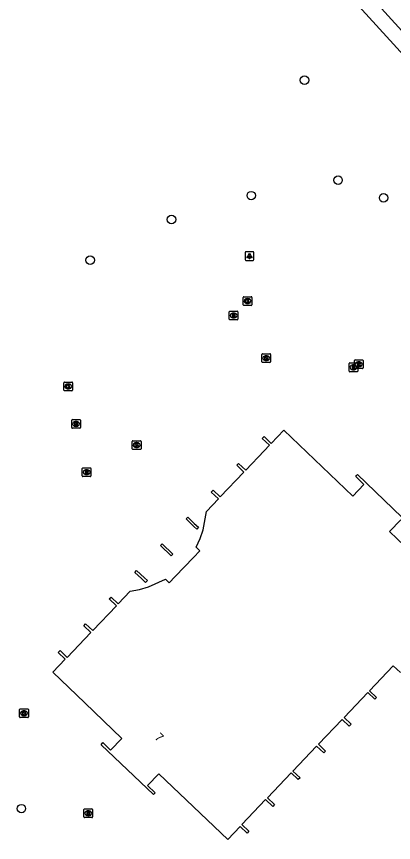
# Model space of a CAD drawing. Extents: x 156061 to 157804, y 383451 to 385640.
# Drawn here: x 156744.7 to 156788, y 385074 to 385169 of the extents above; entities that cross this region are included whole.
import ezdxf

# ---------------------------------------------------------------- set-up
doc = ezdxf.new("R2010")
doc.units = 0
for name, color, linetype in [('IMGEO_Boom', 7, 'Continuous'), ('IMGEO_Groenvoorziening', 7, 'Continuous'), ('IMGEO_Kolk', 7, 'Continuous'), ('IMGEO_Lichtpunt', 7, 'Continuous'), ('IMGEO_Muur', 7, 'Continuous'), ('IMGEO_Pand', 7, 'Continuous'), ('IMGEO_Pand_nummerreeks', 7, 'Continuous'), ('IMGEO_Rioolput', 7, 'Continuous')]:
    doc.layers.add(name, color=color, linetype=linetype)

msp = doc.modelspace()

# ---------------------------------------------------------------- linework, layer by layer
at = {"layer": 'IMGEO_Boom'}
for centre in [(156777.789, 385161.673), (156781.652, 385150.175), (156771.679, 385148.407), (156786.886, 385148.15), (156762.496, 385145.654), (156753.154, 385140.988), (156745.247, 385077.936)]:
    msp.add_circle(centre, 0.489, dxfattribs=at)
at = {"layer": 'IMGEO_Groenvoorziening'}
for points in [[(156761.368, 385197.864), (156769.389, 385188.869), (156788.986, 385167.342), (156795.719, 385160.38), (156801.201, 385154.555), (156810.516, 385145.054), (156813.592, 385141.799), (156814.804, 385140.338), (156816.368, 385138.907), (156818.343, 385137.378), (156819.322, 385136.23), (156819.794, 385135.425), (156822.114, 385133.429), (156843.396, 385112.468), (156845.278, 385111.354), (156860.479, 385096.242), (156876.719, 385081.077), (156890.203, 385068.13), (156896.136, 385062.583), (156899.441, 385059.57)], [(156717.677, 385063.118), (156717.97, 385063.009), (156717.781, 385062.506), (156718.696, 385062.163), (156718.88, 385062.654), (156870.373, 385006.508), (156870.967, 385006.288), (156875.119, 385016.625), (156892.549, 385064.295), (156865.99, 385088.285), (156852.111, 385101.789), (156804.773, 385147.48), (156780.437, 385174.157), (156759.871, 385196.529)]]:
    msp.add_lwpolyline(points, dxfattribs=at)
at = {"layer": 'IMGEO_Kolk'}
for p, q in [((156770.818, 385136.787), (156771.67, 385136.787)), ((156770.743, 385135.861), (156770.743, 385136.713)), ((156771.67, 385135.787), (156770.818, 385135.787)), ((156771.254, 385136.007), (156771.229, 385136.007)), ((156771.231, 385136.567), (156771.256, 385136.567)), ((156771.744, 385136.713), (156771.744, 385135.861)), ((156772.898, 385129.299), (156772.898, 385130.151)), ((156772.973, 385130.225), (156773.825, 385130.225)), ((156773.899, 385130.151), (156773.899, 385129.299)), ((156773.825, 385129.225), (156772.973, 385129.225)), ((156773.409, 385129.445), (156773.384, 385129.445)), ((156773.386, 385130.005), (156773.411, 385130.005)), ((156750.131, 385126.051), (156750.131, 385126.903)), ((156750.206, 385126.977), (156751.058, 385126.977)), ((156750.619, 385126.757), (156750.644, 385126.757)), ((156751.132, 385126.903), (156751.132, 385126.051)), ((156751.058, 385125.977), (156750.206, 385125.977)), ((156750.642, 385126.197), (156750.617, 385126.197)), ((156758.003, 385119.308), (156758.003, 385120.16)), ((156758.078, 385120.234), (156758.93, 385120.234)), ((156758.491, 385120.014), (156758.516, 385120.014)), ((156759.004, 385120.16), (156759.004, 385119.308)), ((156758.93, 385119.234), (156758.078, 385119.234)), ((156758.514, 385119.454), (156758.489, 385119.454)), ((156745.049, 385088.477), (156745.049, 385089.329)), ((156745.124, 385089.403), (156745.976, 385089.403)), ((156746.05, 385089.329), (156746.05, 385088.477)), ((156745.976, 385088.403), (156745.124, 385088.403)), ((156745.56, 385088.623), (156745.535, 385088.623)), ((156745.537, 385089.183), (156745.562, 385089.183))]:
    msp.add_line(p, q, dxfattribs=at)
for points in [[(156770.818, 385136.787), (156771.67, 385136.787)], [(156770.743, 385135.861), (156770.743, 385136.713)], [(156771.67, 385135.787), (156770.818, 385135.787)], [(156771.064, 385136.487), (156771.187, 385136.487), (156771.187, 385136.336), (156771.317, 385136.487), (156771.481, 385136.487), (156771.335, 385136.336), (156771.488, 385136.087), (156771.336, 385136.087), (156771.251, 385136.251), (156771.187, 385136.184), (156771.187, 385136.087), (156771.064, 385136.087), (156771.064, 385136.487)], [(156771.744, 385136.713), (156771.744, 385135.861)], [(156772.898, 385129.299), (156772.898, 385130.151)], [(156772.973, 385130.225), (156773.825, 385130.225)], [(156773.899, 385130.151), (156773.899, 385129.299)], [(156773.825, 385129.225), (156772.973, 385129.225)], [(156773.219, 385129.925), (156773.342, 385129.925), (156773.342, 385129.774), (156773.472, 385129.925), (156773.636, 385129.925), (156773.49, 385129.774), (156773.643, 385129.525), (156773.491, 385129.525), (156773.406, 385129.689), (156773.342, 385129.622), (156773.342, 385129.525), (156773.219, 385129.525), (156773.219, 385129.925)], [(156750.131, 385126.051), (156750.131, 385126.903)], [(156750.206, 385126.977), (156751.058, 385126.977)], [(156750.452, 385126.677), (156750.575, 385126.677), (156750.575, 385126.526), (156750.705, 385126.677), (156750.869, 385126.677), (156750.723, 385126.526), (156750.876, 385126.277), (156750.724, 385126.277), (156750.639, 385126.441), (156750.575, 385126.374), (156750.575, 385126.277), (156750.452, 385126.277), (156750.452, 385126.677)], [(156751.132, 385126.903), (156751.132, 385126.051)], [(156751.058, 385125.977), (156750.206, 385125.977)], [(156758.003, 385119.308), (156758.003, 385120.16)], [(156758.078, 385120.234), (156758.93, 385120.234)], [(156758.324, 385119.934), (156758.447, 385119.934), (156758.447, 385119.783), (156758.577, 385119.934), (156758.741, 385119.934), (156758.595, 385119.783), (156758.748, 385119.534), (156758.596, 385119.534), (156758.511, 385119.698), (156758.447, 385119.631), (156758.447, 385119.534), (156758.324, 385119.534), (156758.324, 385119.934)], [(156759.004, 385120.16), (156759.004, 385119.308)], [(156758.93, 385119.234), (156758.078, 385119.234)], [(156745.049, 385088.477), (156745.049, 385089.329)], [(156745.124, 385089.403), (156745.976, 385089.403)], [(156746.05, 385089.329), (156746.05, 385088.477)], [(156745.976, 385088.403), (156745.124, 385088.403)], [(156745.37, 385089.103), (156745.493, 385089.103), (156745.493, 385088.952), (156745.623, 385089.103), (156745.787, 385089.103), (156745.641, 385088.952), (156745.794, 385088.703), (156745.642, 385088.703), (156745.557, 385088.867), (156745.493, 385088.8), (156745.493, 385088.703), (156745.37, 385088.703), (156745.37, 385089.103)]]:
    msp.add_lwpolyline(points, dxfattribs=at)
for centre, start, end in [((156770.82, 385136.711), 91.55205, 178.44795), ((156770.82, 385136.711), 91.55205, 178.44795), ((156771.668, 385136.711), 1.55205, 88.44795), ((156771.668, 385136.711), 1.55205, 88.44795), ((156770.82, 385135.863), 181.55205, 268.44795), ((156770.82, 385135.863), 181.55205, 268.44795), ((156771.668, 385135.863), 271.55205, 358.44795), ((156771.668, 385135.863), 271.55205, 358.44795), ((156772.975, 385130.149), 91.55205, 178.44795), ((156772.975, 385130.149), 91.55205, 178.44795), ((156773.823, 385130.149), 1.55205, 88.44795), ((156773.823, 385130.149), 1.55205, 88.44795), ((156772.975, 385129.301), 181.55205, 268.44795), ((156772.975, 385129.301), 181.55205, 268.44795), ((156773.823, 385129.301), 271.55205, 358.44795), ((156773.823, 385129.301), 271.55205, 358.44795), ((156750.208, 385126.901), 91.55205, 178.44795), ((156750.208, 385126.901), 91.55205, 178.44795), ((156751.056, 385126.901), 1.55205, 88.44795), ((156751.056, 385126.901), 1.55205, 88.44795), ((156750.208, 385126.053), 181.55205, 268.44795), ((156750.208, 385126.053), 181.55205, 268.44795), ((156751.056, 385126.053), 271.55205, 358.44795), ((156751.056, 385126.053), 271.55205, 358.44795), ((156758.08, 385120.158), 91.55205, 178.44795), ((156758.08, 385120.158), 91.55205, 178.44795), ((156758.928, 385120.158), 1.55205, 88.44795), ((156758.928, 385120.158), 1.55205, 88.44795), ((156758.08, 385119.31), 181.55205, 268.44795), ((156758.08, 385119.31), 181.55205, 268.44795), ((156758.928, 385119.31), 271.55205, 358.44795), ((156758.928, 385119.31), 271.55205, 358.44795), ((156745.126, 385089.327), 91.55205, 178.44795), ((156745.126, 385089.327), 91.55205, 178.44795), ((156745.974, 385089.327), 1.55205, 88.44795), ((156745.974, 385089.327), 1.55205, 88.44795), ((156745.126, 385088.479), 181.55205, 268.44795), ((156745.126, 385088.479), 181.55205, 268.44795), ((156745.974, 385088.479), 271.55205, 358.44795), ((156745.974, 385088.479), 271.55205, 358.44795)]:
    msp.add_arc(centre, 0.0765, start, end, dxfattribs=at)
for centre, major_axis, ratio, start_param, end_param in [((156771.23, 385136.287), (-0.387, 0.002), 0.722429, 4.712389, 7.853982), ((156771.255, 385136.287), (-0.39, 0.002), 0.717154, 1.570796, 4.712389), ((156773.385, 385129.725), (-0.387, 0.002), 0.722429, 4.712389, 7.853982), ((156773.41, 385129.725), (-0.39, 0.002), 0.717154, 1.570796, 4.712389), ((156750.618, 385126.477), (-0.387, 0.002), 0.722429, 4.712389, 7.853982), ((156750.643, 385126.477), (-0.39, 0.002), 0.717154, 1.570796, 4.712389), ((156758.49, 385119.734), (-0.387, 0.002), 0.722429, 4.712389, 7.853982), ((156758.515, 385119.734), (-0.39, 0.002), 0.717154, 1.570796, 4.712389), ((156745.536, 385088.903), (-0.387, 0.002), 0.722429, 4.712389, 7.853982), ((156745.561, 385088.903), (-0.39, 0.002), 0.717154, 1.570796, 4.712389)]:
    msp.add_ellipse(centre, major_axis=major_axis, ratio=ratio, start_param=start_param, end_param=end_param, dxfattribs=at)
at = {"layer": 'IMGEO_Lichtpunt'}
for p, q in [((156770.972, 385141.864), (156770.972, 385141.057)), ((156770.972, 385141.864), (156770.972, 385141.057)), ((156771.874, 385141.959), (156771.066, 385141.959)), ((156771.874, 385141.959), (156771.066, 385141.959)), ((156771.968, 385141.057), (156771.968, 385141.864)), ((156771.968, 385141.057), (156771.968, 385141.864)), ((156771.066, 385140.963), (156771.874, 385140.963)), ((156771.066, 385140.963), (156771.874, 385140.963))]:
    msp.add_line(p, q, dxfattribs=at)
for points in [[(156771.346, 385141.528), (156771.385, 385141.5), (156771.197, 385141.238), (156771.159, 385141.265), (156771.346, 385141.528)], [(156771.448, 385141.48), (156771.495, 385141.48), (156771.495, 385141.158), (156771.448, 385141.158), (156771.448, 385141.48)], [(156771.558, 385141.5), (156771.596, 385141.527), (156771.783, 385141.265), (156771.744, 385141.237), (156771.558, 385141.5)]]:
    msp.add_lwpolyline(points, dxfattribs=at)
msp.add_circle((156771.471, 385141.662), 0.0994, dxfattribs=at)
for centre, start, end in [((156771.066, 385141.864), 90, 180), ((156771.066, 385141.864), 90, 180), ((156771.874, 385141.864), 0, 90), ((156771.874, 385141.864), 0, 90), ((156771.066, 385141.057), 180, 270), ((156771.066, 385141.057), 180, 270), ((156771.874, 385141.057), 270, 0), ((156771.874, 385141.057), 270, 360)]:
    msp.add_arc(centre, 0.0946, start, end, dxfattribs=at)
at = {"layer": 'IMGEO_Muur'}
msp.add_lwpolyline([(156875.119, 385016.625), (156892.549, 385064.295), (156865.99, 385088.285), (156852.111, 385101.789), (156804.773, 385147.48), (156780.437, 385174.157), (156759.871, 385196.529)], dxfattribs=at)
at = {"layer": 'IMGEO_Pand'}
for points in [[(156776.469, 385082.264), (156777.28, 385081.491), (156777.073, 385081.274), (156776.262, 385082.047), (156773.535, 385079.189), (156774.346, 385078.416), (156774.139, 385078.199), (156773.328, 385078.972), (156770.601, 385076.114), (156771.412, 385075.341), (156771.205, 385075.124), (156770.394, 385075.897), (156768.968, 385074.402), (156761.046, 385081.957), (156759.76, 385080.603), (156760.645, 385079.768), (156760.425, 385079.549), (156754.405, 385085.261), (156754.626, 385085.527), (156755.503, 385084.662), (156756.803, 385086.009), (156754.676, 385088.049), (156752.53, 385090.107), (156748.874, 385093.614), (156750.296, 385095.106), (156749.486, 385095.879), (156749.699, 385096.103), (156750.509, 385095.33), (156753.234, 385098.19), (156752.424, 385098.963), (156752.638, 385099.187), (156753.448, 385098.414), (156756.166, 385101.267), (156755.356, 385102.04), (156755.563, 385102.257), (156756.373, 385101.484), (156757.769, 385102.949), (156758.836, 385103.138), (156759.851, 385103.431), (156761.8, 385104.331), (156762.254, 385103.908), (156762.945, 385104.624), (156765.052, 385106.806), (156765.778, 385107.557), (156765.322, 385107.998), (156765.792, 385108.99), (156766.141, 385110), (156766.514, 385112.109), (156767.894, 385113.558), (156767.083, 385114.331), (156767.29, 385114.548), (156768.101, 385113.775), (156770.825, 385116.635), (156770.014, 385117.408), (156770.221, 385117.625), (156771.032, 385116.852), (156773.16, 385119.087), (156773.756, 385119.713), (156772.945, 385120.486), (156773.152, 385120.703), (156773.963, 385119.93), (156775.408, 385121.447), (156783.345, 385113.844), (156784.629, 385115.205), (156783.69, 385116.135), (156783.785, 385116.24), (156783.897, 385116.364), (156790.031, 385110.462)], [(156765.401, 385110.061), (156765.065, 385110.37), (156764.175, 385111.241), (156764.37, 385111.451), (156765.12, 385110.733), (156765.605, 385110.279), (156765.401, 385110.061)], [(156788.853, 385111.154), (156787.582, 385109.808), (156795.507, 385102.218)], [(156761.243, 385108.182), (156761.444, 385108.383), (156762.656, 385107.209), (156762.467, 385106.999), (156761.243, 385108.182)], [(156758.303, 385105.094), (156758.501, 385105.323), (156759.413, 385104.478), (156759.74, 385104.157), (156759.526, 385103.94), (156759.041, 385104.39), (156758.303, 385105.094)], [(156788.815, 385093.581), (156788.004, 385094.354), (156785.277, 385091.496), (156786.088, 385090.723), (156785.881, 385090.506), (156785.07, 385091.279), (156782.337, 385088.414), (156783.148, 385087.641), (156782.94, 385087.424), (156782.129, 385088.197), (156779.396, 385085.332), (156780.207, 385084.559), (156780, 385084.341), (156779.189, 385085.114), (156776.469, 385082.264)]]:
    msp.add_lwpolyline(points, dxfattribs=at)
at = {"layer": 'IMGEO_Rioolput'}
for p, q in [((156769.145, 385134.201), (156769.145, 385135.053)), ((156769.22, 385135.127), (156770.072, 385135.127)), ((156769.633, 385134.907), (156769.658, 385134.907)), ((156770.146, 385135.053), (156770.146, 385134.201)), ((156770.072, 385134.127), (156769.22, 385134.127)), ((156769.656, 385134.347), (156769.631, 385134.347)), ((156782.995, 385129.167), (156783.847, 385129.167)), ((156783.533, 385128.594), (156783.533, 385129.446)), ((156783.608, 385129.52), (156784.46, 385129.52)), ((156784.021, 385129.3), (156784.046, 385129.3)), ((156784.534, 385129.446), (156784.534, 385128.594)), ((156782.92, 385128.241), (156782.92, 385129.093)), ((156783.431, 385128.387), (156783.406, 385128.387)), ((156783.408, 385128.947), (156783.433, 385128.947)), ((156784.46, 385128.52), (156783.608, 385128.52)), ((156783.921, 385129.093), (156783.921, 385128.241)), ((156784.044, 385128.74), (156784.019, 385128.74)), ((156783.847, 385128.167), (156782.995, 385128.167)), ((156751.033, 385121.738), (156751.033, 385122.59)), ((156751.108, 385122.664), (156751.96, 385122.664)), ((156752.034, 385122.59), (156752.034, 385121.738)), ((156751.96, 385121.664), (156751.108, 385121.664)), ((156751.544, 385121.884), (156751.519, 385121.884)), ((156751.521, 385122.444), (156751.546, 385122.444)), ((156752.251, 385116.188), (156752.251, 385117.04)), ((156752.326, 385117.114), (156753.178, 385117.114)), ((156752.739, 385116.894), (156752.764, 385116.894)), ((156753.252, 385117.04), (156753.252, 385116.188)), ((156753.178, 385116.114), (156752.326, 385116.114)), ((156752.762, 385116.334), (156752.737, 385116.334)), ((156752.511, 385077.904), (156753.363, 385077.904)), ((156752.436, 385076.978), (156752.436, 385077.83)), ((156753.363, 385076.904), (156752.511, 385076.904)), ((156752.947, 385077.124), (156752.922, 385077.124)), ((156752.924, 385077.684), (156752.949, 385077.684)), ((156753.437, 385077.83), (156753.437, 385076.978))]:
    msp.add_line(p, q, dxfattribs=at)
for points in [[(156769.145, 385134.201), (156769.145, 385135.053)], [(156769.22, 385135.127), (156770.072, 385135.127)], [(156769.734, 385134.825), (156769.482, 385134.827), (156769.482, 385134.427)], [(156770.146, 385135.053), (156770.146, 385134.201)], [(156770.072, 385134.127), (156769.22, 385134.127)], [(156769.482, 385134.427), (156769.606, 385134.427), (156769.606, 385134.589), (156769.617, 385134.589)], [(156769.66, 385134.746), (156769.606, 385134.746), (156769.606, 385134.665)], [(156769.606, 385134.665), (156769.658, 385134.665)], [(156769.664, 385134.56), (156769.735, 385134.427), (156769.875, 385134.427), (156769.81, 385134.553)], [(156782.995, 385129.167), (156783.847, 385129.167)], [(156783.533, 385128.594), (156783.533, 385129.446)], [(156783.608, 385129.52), (156784.46, 385129.52)], [(156784.122, 385129.218), (156783.87, 385129.22), (156783.87, 385128.82)], [(156784.048, 385129.139), (156783.994, 385129.139), (156783.994, 385129.058)], [(156784.534, 385129.446), (156784.534, 385128.594)], [(156782.92, 385128.241), (156782.92, 385129.093)], [(156783.509, 385128.865), (156783.257, 385128.867), (156783.257, 385128.467)], [(156783.257, 385128.467), (156783.381, 385128.467), (156783.381, 385128.629), (156783.392, 385128.629)], [(156783.435, 385128.786), (156783.381, 385128.786), (156783.381, 385128.705)], [(156783.381, 385128.705), (156783.433, 385128.705)], [(156783.439, 385128.6), (156783.51, 385128.467), (156783.65, 385128.467), (156783.585, 385128.593)], [(156784.46, 385128.52), (156783.608, 385128.52)], [(156783.87, 385128.82), (156783.994, 385128.82), (156783.994, 385128.982), (156784.005, 385128.982)], [(156783.921, 385129.093), (156783.921, 385128.241)], [(156783.994, 385129.058), (156784.046, 385129.058)], [(156784.052, 385128.953), (156784.123, 385128.82), (156784.263, 385128.82), (156784.198, 385128.946)], [(156783.847, 385128.167), (156782.995, 385128.167)], [(156751.033, 385121.738), (156751.033, 385122.59)], [(156751.108, 385122.664), (156751.96, 385122.664)], [(156752.034, 385122.59), (156752.034, 385121.738)], [(156751.96, 385121.664), (156751.108, 385121.664)], [(156751.622, 385122.362), (156751.37, 385122.364), (156751.37, 385121.964)], [(156751.37, 385121.964), (156751.494, 385121.964), (156751.494, 385122.126), (156751.505, 385122.126)], [(156751.548, 385122.283), (156751.494, 385122.283), (156751.494, 385122.202)], [(156751.494, 385122.202), (156751.546, 385122.202)], [(156751.552, 385122.097), (156751.623, 385121.964), (156751.763, 385121.964), (156751.698, 385122.09)], [(156752.251, 385116.188), (156752.251, 385117.04)], [(156752.326, 385117.114), (156753.178, 385117.114)], [(156752.84, 385116.812), (156752.588, 385116.814), (156752.588, 385116.414)], [(156753.252, 385117.04), (156753.252, 385116.188)], [(156753.178, 385116.114), (156752.326, 385116.114)], [(156752.588, 385116.414), (156752.712, 385116.414), (156752.712, 385116.576), (156752.723, 385116.576)], [(156752.766, 385116.733), (156752.712, 385116.733), (156752.712, 385116.652)], [(156752.712, 385116.652), (156752.764, 385116.652)], [(156752.77, 385116.547), (156752.841, 385116.414), (156752.981, 385116.414), (156752.916, 385116.54)], [(156752.511, 385077.904), (156753.363, 385077.904)], [(156752.436, 385076.978), (156752.436, 385077.83)], [(156753.363, 385076.904), (156752.511, 385076.904)], [(156753.025, 385077.602), (156752.773, 385077.604), (156752.773, 385077.204)], [(156752.773, 385077.204), (156752.897, 385077.204), (156752.897, 385077.366), (156752.908, 385077.366)], [(156752.951, 385077.523), (156752.897, 385077.523), (156752.897, 385077.442)], [(156752.897, 385077.442), (156752.949, 385077.442)], [(156752.955, 385077.337), (156753.026, 385077.204), (156753.166, 385077.204), (156753.101, 385077.33)], [(156753.437, 385077.83), (156753.437, 385076.978)]]:
    msp.add_lwpolyline(points, dxfattribs=at)
for centre, radius, start, end in [((156769.222, 385135.051), 0.0765, 91.55205, 178.44795), ((156769.222, 385135.051), 0.0765, 91.55205, 178.44795), ((156769.733, 385134.715), 0.109, 350.36119, 89.41601), ((156770.07, 385135.051), 0.0765, 1.55205, 88.44795), ((156770.07, 385135.051), 0.0765, 1.55205, 88.44795), ((156769.222, 385134.203), 0.0765, 181.55205, 268.44795), ((156769.222, 385134.203), 0.0765, 181.55205, 268.44795), ((156769.616, 385134.536), 0.0533, 26.02933, 88.69889), ((156769.642, 385134.854), 0.19, 274.7715, 282.96867), ((156769.666, 385134.65), 0.0964, 77.00612, 93.18647), ((156769.68, 385134.707), 0.0378, 276.66336, 79.67722), ((156769.731, 385134.715), 0.112, 277.58423, 350.98172), ((156769.715, 385134.5), 0.108, 29.51342, 73.79051), ((156770.07, 385134.203), 0.0765, 271.55205, 358.44795), ((156770.07, 385134.203), 0.0765, 271.55205, 358.44795), ((156782.997, 385129.091), 0.0765, 91.55205, 178.44795), ((156782.997, 385129.091), 0.0765, 91.55205, 178.44795), ((156783.61, 385129.444), 0.0765, 91.55205, 178.44795), ((156783.61, 385129.444), 0.0765, 91.55205, 178.44795), ((156783.845, 385129.091), 0.0765, 1.55205, 88.44795), ((156783.845, 385129.091), 0.0765, 1.55205, 88.44795), ((156784.054, 385129.043), 0.0964, 77.00612, 93.18647), ((156784.068, 385129.1), 0.0378, 276.66336, 79.67722), ((156784.121, 385129.108), 0.109, 350.36119, 89.41601), ((156784.458, 385129.444), 0.0765, 1.55205, 88.44795), ((156784.458, 385129.444), 0.0765, 1.55205, 88.44795), ((156782.997, 385128.243), 0.0765, 181.55205, 268.44795), ((156782.997, 385128.243), 0.0765, 181.55205, 268.44795), ((156783.391, 385128.576), 0.0533, 26.02933, 88.69889), ((156783.417, 385128.894), 0.19, 274.7715, 282.96867), ((156783.441, 385128.69), 0.0964, 77.00612, 93.18647), ((156783.455, 385128.747), 0.0378, 276.66336, 79.67722), ((156783.508, 385128.755), 0.109, 350.36119, 89.41601), ((156783.506, 385128.755), 0.112, 277.58423, 350.98172), ((156783.49, 385128.54), 0.108, 29.51342, 73.79051), ((156783.61, 385128.596), 0.0765, 181.55205, 268.44795), ((156783.61, 385128.596), 0.0765, 181.55205, 268.44795), ((156783.845, 385128.243), 0.0765, 271.55205, 358.44795), ((156783.845, 385128.243), 0.0765, 271.55205, 358.44795), ((156784.004, 385128.929), 0.0533, 26.02933, 88.69889), ((156784.03, 385129.247), 0.19, 274.7715, 282.96867), ((156784.119, 385129.108), 0.112, 277.58423, 350.98172), ((156784.103, 385128.893), 0.108, 29.51342, 73.79051), ((156784.458, 385128.596), 0.0765, 271.55205, 358.44795), ((156784.458, 385128.596), 0.0765, 271.55205, 358.44795), ((156751.11, 385122.588), 0.0765, 91.55205, 178.44795), ((156751.11, 385122.588), 0.0765, 91.55205, 178.44795), ((156751.958, 385122.588), 0.0765, 1.55205, 88.44795), ((156751.958, 385122.588), 0.0765, 1.55205, 88.44795), ((156751.11, 385121.74), 0.0765, 181.55205, 268.44795), ((156751.11, 385121.74), 0.0765, 181.55205, 268.44795), ((156751.504, 385122.073), 0.0533, 26.02933, 88.69889), ((156751.53, 385122.391), 0.19, 274.7715, 282.96867), ((156751.554, 385122.187), 0.0964, 77.00612, 93.18647), ((156751.568, 385122.244), 0.0378, 276.66336, 79.67722), ((156751.621, 385122.252), 0.109, 350.36119, 89.41601), ((156751.619, 385122.252), 0.112, 277.58423, 350.98172), ((156751.603, 385122.037), 0.108, 29.51342, 73.79051), ((156751.958, 385121.74), 0.0765, 271.55205, 358.44795), ((156751.958, 385121.74), 0.0765, 271.55205, 358.44795), ((156752.328, 385117.038), 0.0765, 91.55205, 178.44795), ((156752.328, 385117.038), 0.0765, 91.55205, 178.44795), ((156752.839, 385116.702), 0.109, 350.36119, 89.41601), ((156753.176, 385117.038), 0.0765, 1.55205, 88.44795), ((156753.176, 385117.038), 0.0765, 1.55205, 88.44795), ((156752.328, 385116.19), 0.0765, 181.55205, 268.44795), ((156752.328, 385116.19), 0.0765, 181.55205, 268.44795), ((156752.722, 385116.523), 0.0533, 26.02933, 88.69889), ((156752.748, 385116.841), 0.19, 274.7715, 282.96867), ((156752.772, 385116.637), 0.0964, 77.00612, 93.18647), ((156752.786, 385116.694), 0.0378, 276.66336, 79.67722), ((156752.837, 385116.702), 0.112, 277.58423, 350.98172), ((156752.821, 385116.487), 0.108, 29.51342, 73.79051), ((156753.176, 385116.19), 0.0765, 271.55205, 358.44795), ((156753.176, 385116.19), 0.0765, 271.55205, 358.44795), ((156752.513, 385077.828), 0.0765, 91.55205, 178.44795), ((156752.513, 385077.828), 0.0765, 91.55205, 178.44795), ((156753.361, 385077.828), 0.0765, 1.55205, 88.44795), ((156753.361, 385077.828), 0.0765, 1.55205, 88.44795), ((156752.513, 385076.98), 0.0765, 181.55205, 268.44795), ((156752.513, 385076.98), 0.0765, 181.55205, 268.44795), ((156752.907, 385077.313), 0.0533, 26.02933, 88.69889), ((156752.933, 385077.631), 0.19, 274.7715, 282.96867), ((156752.957, 385077.427), 0.0964, 77.00612, 93.18647), ((156752.971, 385077.484), 0.0378, 276.66336, 79.67722), ((156753.024, 385077.492), 0.109, 350.36119, 89.41601), ((156753.022, 385077.492), 0.112, 277.58423, 350.98172), ((156753.006, 385077.277), 0.108, 29.51342, 73.79051), ((156753.361, 385076.98), 0.0765, 271.55205, 358.44795), ((156753.361, 385076.98), 0.0765, 271.55205, 358.44795)]:
    msp.add_arc(centre, radius, start, end, dxfattribs=at)
for centre, major_axis, ratio, start_param, end_param in [((156769.632, 385134.627), (-0.387, 0.002), 0.722429, 4.712389, 7.853982), ((156769.657, 385134.627), (-0.39, 0.002), 0.717154, 1.570796, 4.712389), ((156784.02, 385129.02), (-0.387, 0.002), 0.722429, 4.712389, 7.853982), ((156784.045, 385129.02), (-0.39, 0.002), 0.717154, 1.570796, 4.712389), ((156783.407, 385128.667), (-0.387, 0.002), 0.722429, 4.712389, 7.853982), ((156783.432, 385128.667), (-0.39, 0.002), 0.717154, 1.570796, 4.712389), ((156751.52, 385122.164), (-0.387, 0.002), 0.722429, 4.712389, 7.853982), ((156751.545, 385122.164), (-0.39, 0.002), 0.717154, 1.570796, 4.712389), ((156752.738, 385116.614), (-0.387, 0.002), 0.722429, 4.712389, 7.853982), ((156752.763, 385116.614), (-0.39, 0.002), 0.717154, 1.570796, 4.712389), ((156752.923, 385077.404), (-0.387, 0.002), 0.722429, 4.712389, 7.853982), ((156752.948, 385077.404), (-0.39, 0.002), 0.717154, 1.570796, 4.712389)]:
    msp.add_ellipse(centre, major_axis=major_axis, ratio=ratio, start_param=start_param, end_param=end_param, dxfattribs=at)

# ---------------------------------------------------------------- texts
at = {"layer": 'IMGEO_Pand_nummerreeks'}
msp.add_text('7', height=1, rotation=316.35675, dxfattribs=at).set_placement((156760.493, 385086.032))

doc.saveas('drawing.dxf')
